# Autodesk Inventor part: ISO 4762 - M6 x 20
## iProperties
Comments: To add or edit properties for Autodesk Inventor files, use iProperties.
Created: 2004-08
Part Number: ISO 4762 - M6 x 20
Vendor: Autodesk Inc.
Document SubType Name: Modeling
Designer: John Blackburn
Material: Default
Description: Hexagon Socket Head Cap Screw
Standard: ISO 4762
Alert: To add or edit properties for Autodesk Inventor files, use iProperties.
Control State: 0
Master: False
Checked Out: False
Shininess: 64.0
Length Units: 11269
Angle Units: 11279
Time Units: 11290
Mass Units: 11283
Length Display Precision: 3
Angle Display Precision: 2
Compacted: True
EGR: 1
Density: 0.0
Volumn: 0.0
Area: 0.0
PropertySet Name: Model Information
Author: John Blackburn
Revision Number: 8
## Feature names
1. Body [Revolution]
2. Slot [Extrusion]
3. Fillet1
4. Chamfer1
